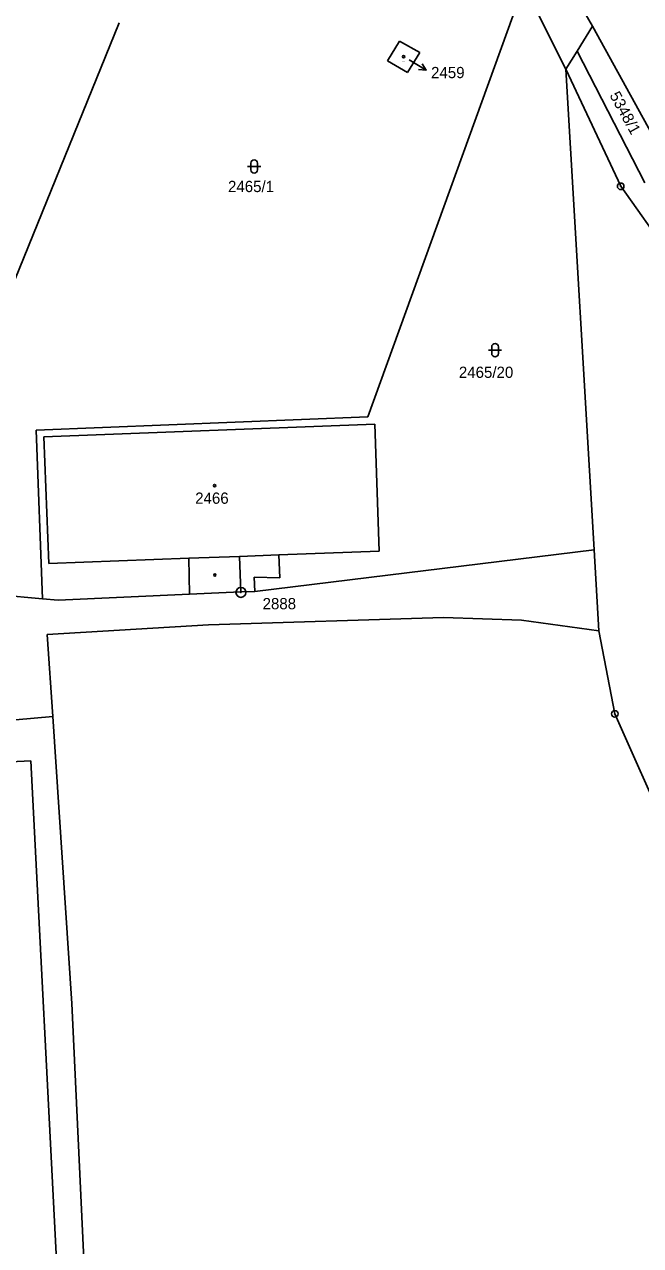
# Model space of a CAD drawing. Extents: x -822293 to -820259, y -1071573 to -1068794.
# Drawn here: x -820740.1 to -820647, y -1070379.8 to -1070195.1 of the extents above; entities that cross this region are included whole.
import ezdxf

# ---------------------------------------------------------------- set-up
doc = ezdxf.new("R2010")
doc.units = 0
for name, color, linetype in [('Vrstva 1', 7, 'Continuous'), ('Vrstva 16', 7, 'Continuous'), ('Vrstva 17', 7, 'Continuous'), ('Vrstva 18', 7, 'Continuous'), ('Vrstva 19', 7, 'Continuous'), ('Vrstva 2', 7, 'Continuous'), ('Vrstva 24', 7, 'Continuous'), ('Vrstva 25', 7, 'Continuous'), ('Vrstva 3', 7, 'Continuous')]:
    doc.layers.add(name, color=color, linetype=linetype)

msp = doc.modelspace()

# ---------------------------------------------------------------- linework, layer by layer
at = {"layer": 'Vrstva 1'}
for p, q in [((-820673.33, -1070162.02), (-820654.29, -1070195.41)), ((-820664.64, -1070189.27), (-820688.2, -1070254.49)), ((-820658.33, -1070201.92), (-820664.64, -1070189.27)), ((-820654.29, -1070195.41), (-820656.6, -1070199.2)), ((-820641.7, -1070218.3), (-820654.29, -1070195.41)), ((-820656.6, -1070199.2), (-820658.33, -1070201.92)), ((-820646.39, -1070219.08), (-820656.6, -1070199.2)), ((-820650.02, -1070219.62), (-820658.33, -1070201.92)), ((-820654.04, -1070274.58), (-820658.33, -1070201.92)), ((-820638.99, -1070235.18), (-820650.02, -1070219.62)), ((-820688.2, -1070254.49), (-820738.31, -1070256.5)), ((-820738.31, -1070256.5), (-820737.36, -1070281.98)), ((-820654.04, -1070274.58), (-820705.26, -1070280.85)), ((-820701.5, -1070278.81), (-820701.63, -1070275.33)), ((-820653.32, -1070286.84), (-820654.04, -1070274.58)), ((-820705.26, -1070280.85), (-820705.36, -1070278.7)), ((-820705.36, -1070278.7), (-820701.5, -1070278.81)), ((-820737.36, -1070281.98), (-820744, -1070281.37)), ((-820715.14, -1070281.29), (-820735, -1070282.2)), ((-820705.26, -1070280.85), (-820707.38, -1070280.94)), ((-820735, -1070282.2), (-820737.36, -1070281.98)), ((-820712.28, -1070285.91), (-820676.77, -1070284.82)), ((-820676.77, -1070284.82), (-820665, -1070285.2)), ((-820665, -1070285.2), (-820653.32, -1070286.84)), ((-820736.63, -1070287.37), (-820712.28, -1070285.91)), ((-820653.32, -1070286.84), (-820650.91, -1070299.38)), ((-820735.8, -1070299.79), (-820736.63, -1070287.37)), ((-820735.8, -1070299.79), (-820763, -1070302.1)), ((-820732.91, -1070343.18), (-820735.8, -1070299.79)), ((-820650.91, -1070299.38), (-820617.03, -1070375.67)), ((-820729.73, -1070411.24), (-820732.91, -1070343.18))]:
    msp.add_line(p, q, dxfattribs=at)
at = {"layer": 'Vrstva 16'}
msp.add_line((-820681.98, -1070200.5), (-820679.421, -1070202.066), dxfattribs=at)
msp.add_lwpolyline([(-820680.013, -1070201.118), (-820679.421, -1070202.066), (-820680.535, -1070201.971)], dxfattribs=at)
at = {"layer": 'Vrstva 2'}
for p, q in [((-820725.75, -1070194.88), (-820745.8, -1070244.23)), ((-820685.24, -1070200.65), (-820683.41, -1070197.67)), ((-820683.41, -1070197.67), (-820680.38, -1070199.41)), ((-820680.38, -1070199.41), (-820682.21, -1070202.4)), ((-820682.21, -1070202.4), (-820685.24, -1070200.65)), ((-820687.13, -1070255.56), (-820737.16, -1070257.48)), ((-820686.49, -1070274.75), (-820687.13, -1070255.56)), ((-820737.16, -1070257.48), (-820736.4, -1070276.66)), ((-820736.4, -1070276.66), (-820715.25, -1070275.85)), ((-820715.25, -1070275.85), (-820715.14, -1070281.29)), ((-820701.63, -1070275.33), (-820686.49, -1070274.75)), ((-820707.38, -1070280.94), (-820715.14, -1070281.29)), ((-820739.09, -1070306.45), (-820754.22, -1070307.24)), ((-820733.78, -1070409.91), (-820739.09, -1070306.45))]:
    msp.add_line(p, q, dxfattribs=at)
at = {"layer": 'Vrstva 24'}
for centre, radius in [((-820650.02, -1070219.62), 0.5), ((-820650.02, -1070219.62), 0.0327), ((-820707.38, -1070281.01), 0.75), ((-820707.38, -1070281.01), 0.0327), ((-820650.91, -1070299.38), 0.5), ((-820650.91, -1070299.38), 0.0327)]:
    msp.add_circle(centre, radius, dxfattribs=at)
at = {"layer": 'Vrstva 25'}
for p, q in [((-820706.38, -1070216.62), (-820704.38, -1070216.62)), ((-820705.88, -1070217.12), (-820705.88, -1070216.12)), ((-820704.88, -1070217.12), (-820704.88, -1070216.12)), ((-820670, -1070244.401), (-820668, -1070244.401)), ((-820669.5, -1070244.901), (-820669.5, -1070243.901)), ((-820668.5, -1070244.901), (-820668.5, -1070243.901))]:
    msp.add_line(p, q, dxfattribs=at)
for centre in [(-820682.81, -1070200.03), (-820711.35, -1070264.86), (-820711.32, -1070278.39)]:
    msp.add_circle(centre, 0.175, dxfattribs=at)
for centre, start, end in [((-820705.38, -1070216.12), 0, 180), ((-820705.38, -1070217.12), 180, 0), ((-820669, -1070243.901), 0, 180), ((-820669, -1070244.901), 180, 0)]:
    msp.add_arc(centre, 0.5, start, end, dxfattribs=at)
at = {"layer": 'Vrstva 3'}
for p, q in [((-820707.59, -1070275.56), (-820715.25, -1070275.85)), ((-820701.63, -1070275.33), (-820707.59, -1070275.56)), ((-820707.59, -1070275.56), (-820707.38, -1070280.94))]:
    msp.add_line(p, q, dxfattribs=at)

# ---------------------------------------------------------------- texts
at = {"layer": 'Vrstva 16'}
msp.add_text('2459', height=1.7, dxfattribs=at).set_placement((-820678.659, -1070203.27))
at = {"layer": 'Vrstva 17'}
msp.add_text('2888', height=1.7, dxfattribs=at).set_placement((-820704.106, -1070283.56))
at = {"layer": 'Vrstva 18'}
msp.add_text('5348/1', height=1.7, rotation=298.79748, dxfattribs=at).set_placement((-820651.751, -1070205.86))
for s, p in [('2465/1', (-820709.327, -1070220.49)), ('2465/20', (-820674.461, -1070248.58))]:
    msp.add_text(s, height=1.7, dxfattribs=at).set_placement(p)
at = {"layer": 'Vrstva 19'}
for s, height, p in [('2459', 0.1, (-820682.968, -1070200.79)), ('2466', 1.7, (-820714.288, -1070267.61))]:
    msp.add_text(s, height=height, dxfattribs=at).set_placement(p)

doc.saveas('drawing.dxf')
